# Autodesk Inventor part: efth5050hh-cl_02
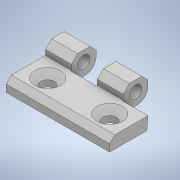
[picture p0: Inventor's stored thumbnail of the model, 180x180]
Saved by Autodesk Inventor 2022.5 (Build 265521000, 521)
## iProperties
Part Number: efth5050hh-cl_02
Material: 一般
Document SubType Name: Modeling
Designer: ImaoCorp
Density: 1 g/cm^3
Appearance: 既定
Author: ImaoCorp
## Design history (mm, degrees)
feature "efth5050hh-cl_02"
node "ソリッド1"
